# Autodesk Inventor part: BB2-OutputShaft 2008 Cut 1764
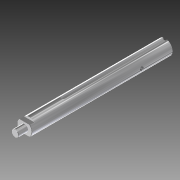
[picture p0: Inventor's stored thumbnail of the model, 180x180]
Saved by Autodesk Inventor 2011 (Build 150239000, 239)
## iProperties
Company: FirstCadLibrary
Shininess: 64.0
Length Units: 11269
Angle Units: 11279
Time Units: 11290
Mass Units: 11283
Length Display Precision: 3
Angle Display Precision: 2
Compacted: True
Part Number: BB2-OutputShaft 2008 Cut 1764
Document SubType Name: Modeling
Created: 2007-01
Material: Steel, Mild
Designer: Ed Sparks
Catalog Web Link: www.banebots.com
Vendor: BaneBots
Mass: 120.202 g
Surface Area: 60.1384 cm^2
Volume: 15.2928 cm^3
Density: 7.86 g/cm^3
Density: 0.0
Volumn: 0.0
Area: 0.0
PropertySet Name: Model Information
Control State: 0
Master: False
Checked Out: False
Author: Ed Sparks
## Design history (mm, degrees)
sketch "Sketch1"
  geometry: C1 r 6.35 at (0, 0); 1 further point
  constraints: 1 centre point, 1 coincident, 1 other
  dimensions: "d0" = 12.7 diameter of C1
extrude "Extrusion1" new body sketch "Sketch1" stored distance "d1" = 127; taper "d2" = 0 deg
sketch "Sketch2"
  geometry: L1 (-4.5, 4.48)-(-4.5, -4.48); L2 (4.5, 4.48)-(4.5, -4.48); L3 (0, 0)-(0, 6.178); A1 r 6.35 centre (0, 0) between (-4.5, -4.48) and (4.5, 4.48) reference
  constraints: 6 end point, 4 point on circle, 2 vertical, 1 parallel, 1 other
  dimensions: "d3" = 9 distance between parallel lines of L2 L1
extrude "Extrusion2" cut sketch "Sketch2" distance "d4" = 4; taper "d5" = 0 deg
sketch "Sketch3"
  geometry: C1 r 3 at (0, 0); A1 r 6.35 centre (0, 0) between (4.5, 4.48) and (-4.5, 4.48) reference
  constraints: 1 centre point, 1 coincident, 1 concentric
  dimensions: "d6" = 6 diameter of C1
extrude "Extrusion3" join sketch "Sketch3" distance "d7" = 8.2; taper "d8" = 0 deg
chamfer "Chamfer1" distance "d9" = 0.25; stored, may be unused: second distance "d10" = 2, angle "d17" = 45 deg
workplane "Work Plane1"
sketch "Sketch4"
  geometry: L1 (6.1, -63.5)-(-6.1, -63.5) reference; L2 (0, -63.5)-(0, -7.87); L3 (-1.588, -63.5)-(-1.587, 30.163); L4 (0, 31.75)-(0, 31.75); L5 (1.587, 30.163)-(1.588, -63.5); A1 r 1.587 centre (0, 30.163) between (0, 31.75) and (-1.587, 30.163); A2 r 1.587 centre (0, 30.163) between (1.587, 30.163) and (0, 31.75); 1 further point
  constraints: 8 end point, 4 point on circle, 4 point on line, 4 tangent, 3 perpendicular, 2 centre point, 1 concentric, 1 midpoint, 1 parallel, 1 other
  dimensions: "d12" = 95.25 distance of point (1.587, 31.75) L5.end; "d13" = 3.175 distance between parallel lines of L5 L3; "d14" = 1.5875 radius of A1
extrude "Extrusion4" cut sketch "Sketch4" distance "d15" = 1.5875; taper "d16" = 0 deg
sketch "Sketch5"
  geometry: C1 r 3.175 at (0, 0); A1 r 6.1 centre (0, 0) between (-5.89, -1.588) and (-5.89, 1.588) reference
  constraints: 1 centre point, 1 coincident
  dimensions: "d18" = 6.35 diameter of C1
extrude "Extrusion5" cut sketch "Sketch5" distance "d19" = 15; taper "d20" = 0 deg
thread "Thread1" dims "d21" = 10, "d22" = 0
sketch "Sketch6"
  geometry: C1 r 3.175 at (0, 0) reference; C2 r 6.35 at (0, 0); A1 r 6.35 centre (0, 0) between (-6.148, -1.588) and (-6.148, 1.588) reference
  constraints: 1 centre point, 1 coincident, 1 concentric
extrude "Extrusion8" cut sketch "Sketch6" distance "d28" = 17.399; taper "d29" = 0 deg
sketch "Sketch8"
  geometry: L1 (6.35, -46.101)-(-6.148, -46.101) reference; C1 r 1.587 at (-0.086, -31.496)
  constraints: 1 centre point
  dimensions: "d30" = 3.175 diameter of C1; "d42" = 14.605 distance from line of L1 C1.centre
extrude "Extrusion9" cut sketch "Sketch8" distance "d31" = 100; taper "d32" = 0 deg
sketch "Sketch9"
  geometry: C1 r 3.224 at (0, 0); A1 r 6.35 centre (0, 0) between (-6.148, -1.588) and (-6.148, 1.587) reference
  constraints: 1 centre point, 1 coincident
  dimensions: "d33" = 6.447 diameter of C1
extrude "Extrusion10" cut sketch "Sketch9" distance "d34" = 20.955; taper "d35" = 0 deg
thread "Thread2" dims "d36" = 10, "d37" = 0
sketch "Sketch10"
  geometry: L1 (-6.148, -1.588)-(-4.763, -1.588) reference; L2 (-4.763, 1.587)-(-6.148, 1.587) reference; L3 (-4.763, -1.588)-(-4.763, 1.587) reference; C1 r 3.224 at (0, 0) reference; C2 r 6.35 at (0, 0); A1 r 6.35 centre (0, 0) between (-6.148, -1.588) and (-6.148, 1.587) reference
  constraints: 1 centre point, 1 coincident, 1 concentric
extrude "Extrusion11" cut sketch "Sketch10" distance "d38" = 3.3782; taper "d39" = 0 deg
sketch "Sketch11"
  geometry: L1 (-6.148, -1.588)-(-4.763, -1.588) reference; L2 (-6.148, 1.587)-(-4.763, 1.587); L3 (-4.763, 1.587)-(-4.763, -1.588); L4 (-6.148, -1.588)-(-4.763, -1.588); C1 r 3.224 at (0, 0) reference; C2 r 3.224 at (0, 0); A1 r 6.35 centre (0, 0) between (-6.148, -1.588) and (-6.148, 1.587) reference; A2 r 6.35 centre (0, 0) between (-6.148, -1.588) and (-6.148, 1.587)
  constraints: 6 end point, 2 centre point, 2 concentric, 2 equal length, 2 point on circle, 1 coincident, 1 perpendicular
extrude "Extrusion12" join sketch "Sketch11" distance "d40" = 0.762; taper "d41" = 0 deg
sketch "Sketch12"
  geometry: L1 (-6.148, -1.588)-(-4.763, -1.588) reference; L2 (-4.763, 1.587)-(-6.148, 1.587) reference; L3 (-4.763, -1.588)-(-4.763, 1.587) reference; L4 (-6.148, -1.588)-(-4.763, -1.588); L5 (-4.763, 1.587)-(-4.763, -1.588); L6 (-4.763, 1.587)-(-6.148, 1.587); C1 r 3.224 at (0, 0) reference; A1 r 6.35 centre (0, 0) between (-6.148, -1.588) and (-6.148, 1.587) reference; A2 r 6.35 centre (0, 0) between (-6.148, -1.588) and (-6.148, 1.587)
  constraints: 6 end point, 2 collinear, 2 point on circle, 1 centre point, 1 concentric, 1 perpendicular
extrude "Extrusion13" cut sketch "Sketch12" distance "d43" = 4.445; taper "d44" = 0 deg
sketch "Sketch13"
  geometry: L1 (-4.763, 1.587)-(-6.148, 1.587) reference; L2 (-4.763, -1.588)-(-4.763, 1.587) reference; L3 (-6.148, -1.588)-(-4.763, -1.588) reference; C1 r 3.224 at (0, 0) reference; A1 r 6.35 centre (0, 0) between (-6.148, -1.588) and (-6.148, 1.587) reference
extrude "Extrusion14" join sketch "Sketch13" distance "d45" = 19.05; taper "d46" = 0 deg
body "Solid1"
other parameters: "d11" = 6.35
